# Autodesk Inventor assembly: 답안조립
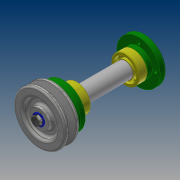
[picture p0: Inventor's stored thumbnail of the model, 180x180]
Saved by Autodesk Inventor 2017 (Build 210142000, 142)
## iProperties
Part Number: 답안조립
Material: 일반
Document SubType Name: Assembly
Designer: 20
Author: 20
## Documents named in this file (11)
- C:\Users\20\Desktop\470818V1010\답안조립.iam
- C:\Users\20\Desktop\470818V1010\본체.ipt
- C:\Users\20\Desktop\470818V1010\앞커버.ipt
- C:\Users\20\Desktop\470818V1010\뒤커버.ipt
- C:\Users\20\Desktop\470818V1010\베어링 15 x 35 x 11.ipt
- C:\Users\20\Desktop\470818V1010\축.ipt
- C:\Users\20\Desktop\470818V1010\멈춤링 15 x 1.ipt
- C:\Users\20\Desktop\470818V1010\키 5 x 5 x 14.ipt
- C:\Users\20\Desktop\470818V1010\V-벨트풀리.ipt
- C:\Users\20\Desktop\470818V1010\와셔.ipt
- C:\Users\20\Desktop\470818V1010\볼트 M6 x 12.ipt
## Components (1 placed, 1 different names)
1. V-벨트풀리:1
